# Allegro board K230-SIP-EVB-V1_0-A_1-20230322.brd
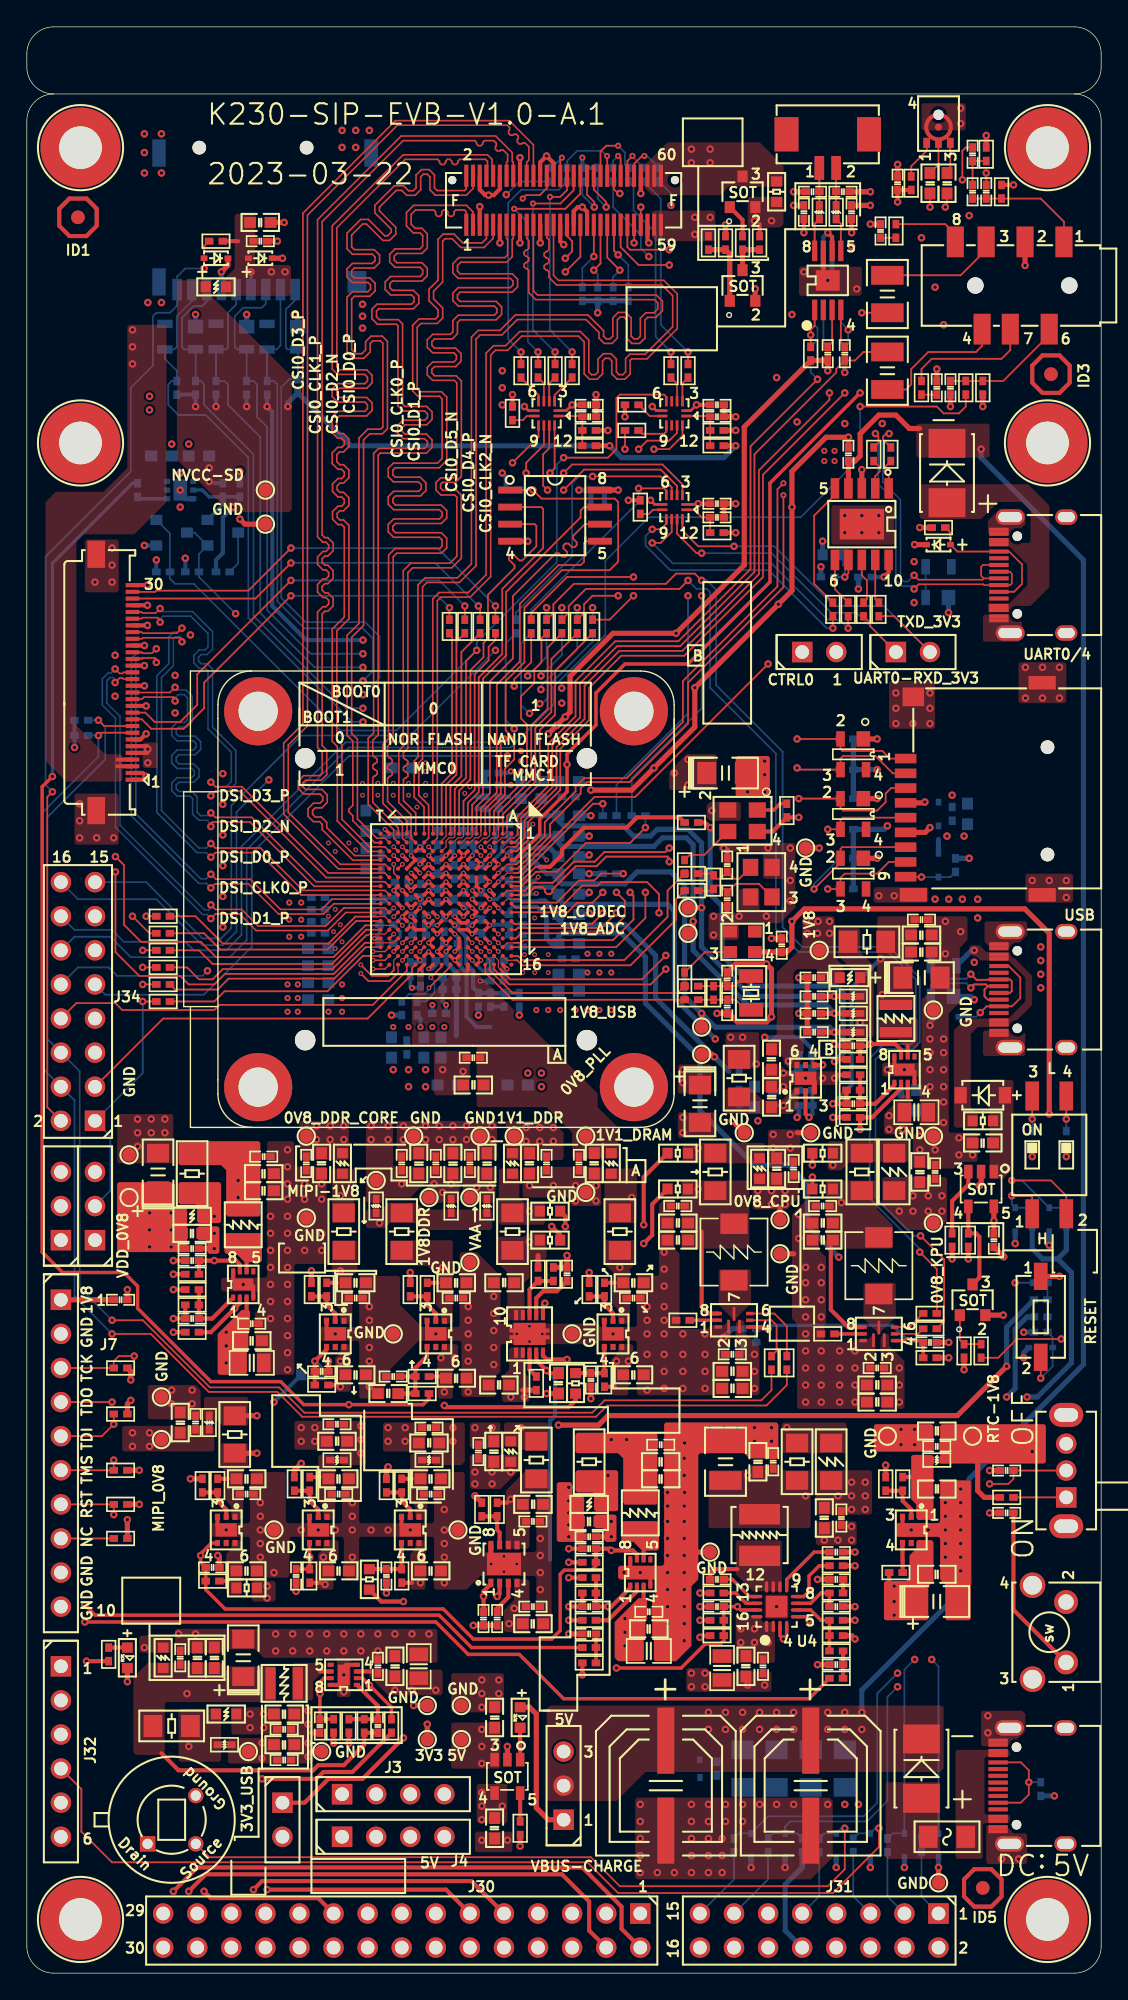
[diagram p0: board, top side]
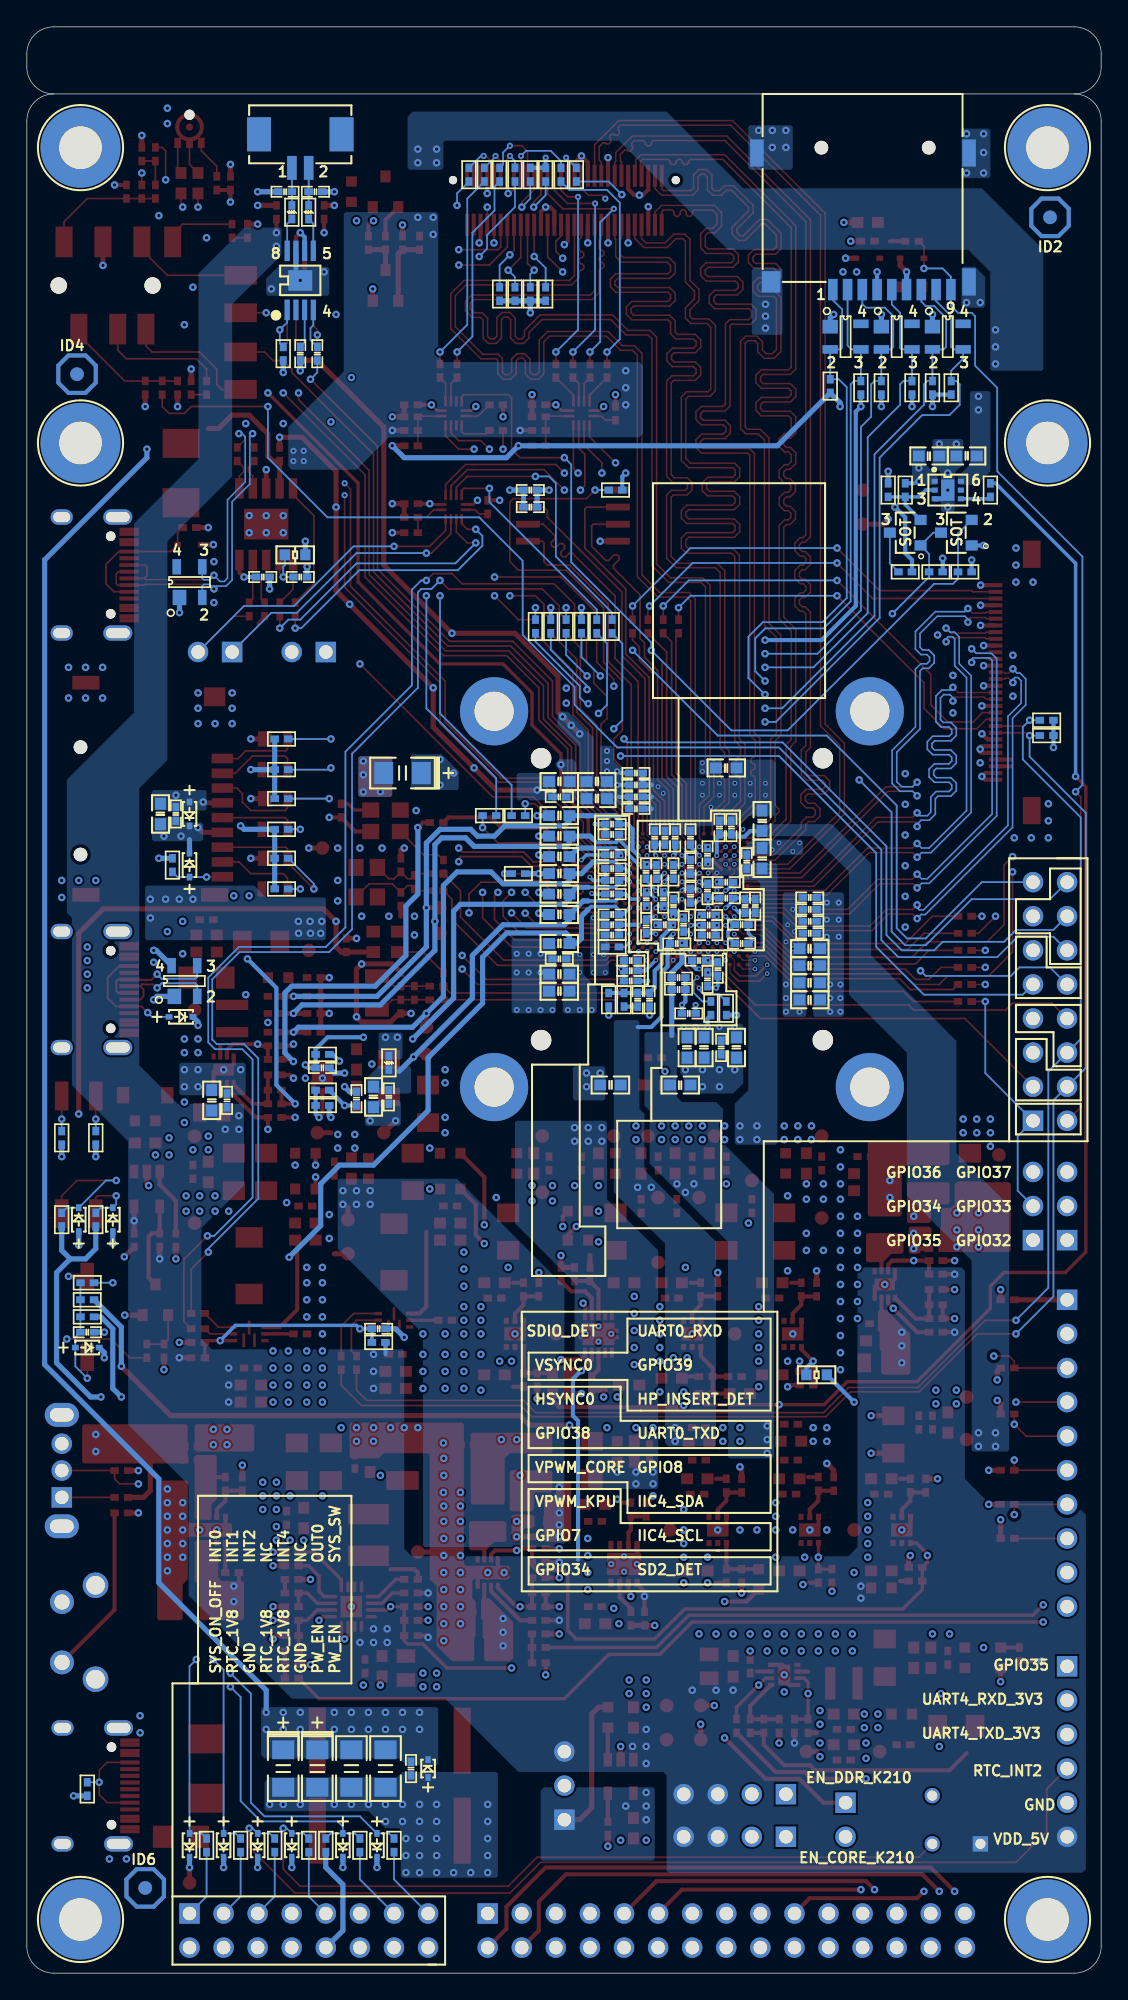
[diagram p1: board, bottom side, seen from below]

Outline 80.07 x 145 mm; copper layers: TOP, GND02, ART03, POWER04, GND05, BOTTOM. Coordinates in mm from the lower left corner of the outline.
Outline path: 2,140 arc(0.59,139.41) 0,138 0,2 arc(0.59,0.59) 2,0 78.07,0 arc(79.48,0.59) 80.07,2 80.07,138 arc(79.48,139.41) 78.07,140 ; 2,140 arc(0.59,140.59) 0,142 0,143 arc(0.59,144.41) 2,145 78.07,145 arc(79.48,144.41) 80.07,143 80.07,142 arc(79.48,140.59) 78.07,140 ; 2,140 78.07,140

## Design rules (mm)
net group ADC0: nets ADC0 HSYNC0
net group ADC1: nets ADC1 VSYNC0
net group ADC2: nets ADC2 N22646851
net group DIFF90: nets USB0_OTG_DN USB0_OTG_DP
net group GPIO20: nets GPIO20 MIPI_DSI_LCD_EN
net group GPIO21: nets GPIO21 MIPI_DSI_D_RST
net group GPIO22: nets GPIO22 MIPI_DSI_T_INT
net group GPIO23: nets GPIO23 MIPI_DSI_T_RST
net group GPIO24_3V3: nets GPIO24_3V3 N22838956
net group GPIO32: nets GPIO32 N22367376
net group GPIO33: nets GPIO33 N22305398
net group GPIO34: nets GPIO34 N22305396
net group GPIO34_1V8: nets GPIO34_1V8 N22897045
net group GPIO35: nets GPIO35 N22305394
net group GPIO35_1V8: nets GPIO35_1V8 N22897025
net group GPIO36: nets GPIO36 N22305392
net group GPIO36_1V8: nets GPIO36_1V8 N22897005
net group GPIO37: nets GPIO37 N22305390
net group GPIO44: nets GPIO44 IIC3_SCL
net group GPIO45: nets GPIO45 IIC3_SDA
net group GPIO48: nets GPIO48 UART4_TXD
net group GPIO49: nets GPIO49 UART4_RXD
net group GPIO59: nets GPIO59 N22647453
net group GPIO60: nets GPIO60 IIC0_SCL
net group GPIO61: nets GPIO61 IIC0_SDA
net group HP_INSERT_DET: nets HP_INSERT_DET N22328764
net group IIC4_SCL: nets IIC4_SCL N23166503
net group IIC4_SDA: nets IIC4_SDA N23166482
net group N22182672: nets N22182672 N22212532
net group N22445143: nets N22445143 N22445145
net group N23147659: nets N23147659 N23147737
net group PG_3V3: nets N23088513 PG_3V3
net group PW_EN: nets N22192931 PW_EN
net group RTC_INT0: nets N22850142 RTC_INT0
net group RTC_INT1: nets N22850140 RTC_INT1
net group RTC_INT2: nets N22850146 RTC_INT2
net group RTC_INT4: nets N22994425 RTC_INT4
net group SYS_SW: nets N22850259 SYS_SW
net group UART0_RXD_3V3: nets N22756731 UART0_RXD_3V3
net group UART0_TXD_3V3: nets N22756757 UART0_TXD_3V3
net group UART4_RXD_3V3: nets N22756876 UART4_RXD_3V3
net group UART4_TXD_3V3: nets N22756879 UART4_TXD_3V3
net group 18MIL: nets JTAG_RST JTAG_TCK M_CLK1 M_CLK2 M_CLK3
net group AVDD1V8_MIPI: nets AVDD1V8_MIPI K230_RSTN RTC_OUT1
net group BUS-QSPI: nets QSPI0_CS0
net group CLK24M_XIN: nets CLK24M_XIN CLK24M_XOUT N22293491 N22778016 N22778033
net group DIFF100: nets DEBUG_DM DEBUG_DP N22756394 N22756396
net group GPIO25: nets GPIO25 N22647230 N228906461
net group GPIO32_1V8: nets GPIO32_1V8 N22647232 N22896944
net group GPIO33_1V8: nets GPIO33_1V8 N22647187 N22896964
net group GPIO37_1V8: nets GPIO37_1V8 N22647219 N22896985
net group GPIO40: nets GPIO40 IIC1_SCL N23166302
net group GPIO41: nets GPIO41 IIC1_SDA N23166270
net group RTC_1V8: nets N22850264 N22850508 RTC_OUT0
net group RTC_CLK_IN: nets N22813541 N22813555 N22813557 RTC_CLK_IN RTC_CLK_OUT

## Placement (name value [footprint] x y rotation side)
C1  330uF/25V  [C1010_8383_6666]  58.42 13.97 180 top
C2  330uF/25V  [C1010_8383_6666]  47.62 13.97 180 top
C3  10uF/16V-1206  [TC1206]  58.42 15.24 270 bottom
C4  10uF/16V-1206  [TC1206]  60.96 15.24 270 bottom
C5  22uF/16V-1206  [C1206]  55.88 15.24 270 bottom
C6  22uF/16V-1206  [C1206]  53.34 15.24 270 bottom
C7  100nF/16V  [C0402]  51.44 15.24 270 bottom
C8  10uF/25V-0603  [C0603]  34.86 10.79 270 top
C9  10uF/25V-0603  [C0603]  34.86 19.05 90 top
C10  10uF/16V-1206  [TC1206]  67.82 27.69 0 top
C11  2.2uF/10V-0603  [C0603]  67.82 29.72 0 top
C12  22uF/6.3V-0603  [C0603]  67.82 36.07 180 top
C13  10uF/10V-0603  [C0603]  67.82 40.39 180 top
C14  100nF/16V  [C0402]  67.82 39.24 180 top
C15  10uF/10V-0603  [C0603]  63.37 42.55 180 top
C16  100nF/16V  [C0402]  63.37 45.09 180 top
C17  10uF/10V-0603  [C0603]  63.37 43.81 180 top
C18  10uF/10V-0603  [C0603]  66.55 59.69 90 top
C19  22uF/6.3V-0603  [C0603]  59.31 54.61 180 top
C20  22uF/6.3V-0603  [C0603]  59.31 55.88 180 top
C21  100nF/16V  [C0402]  67.69 59.69 90 top
C22  100nF/16V  [C0402]  59.31 57.15 180 top
C23  NC  [C0402]  67.31 46.99 0 top
C24  22uF/16V-0805  [C0805]  51.82 22.73 270 top
C25  10uF/10V-0603  [C0603]  53.59 22.86 270 top
C26  100nF/16V  [C0402]  54.86 22.86 90 top
C27  100nF/16V  [C0402]  51.44 29.34 180 top
C28  220uF/6.3V-1210  [C1210]  52.07 38.1 90 top
C29  47uF/6.3V-0603  [C0603]  54.48 38.1 90 top
C30  100nF/16V  [C0402]  55.63 38.1 270 top
C31  10uF/10V-0603  [C0603]  59.44 33.91 270 top
C32  100nF/16V  [C0402]  60.71 33.91 270 top
C35  NC  [C0402]  51.44 27.3 0 top
C36  10nF/16V  [C0402]  60.33 27.3 0 top
C37  10nF/16V  [C0402]  60.33 31.37 0 top
C40  1.2nF/50V  [C0402]  60.33 29.34 180 top
C41  100nF/16V  [C0402]  60.33 22.99 180 top
C42  22uF/6.3V-0603  [C0603]  48.51 54.61 180 top
C43  22uF/6.3V-0603  [C0603]  48.51 55.88 180 top
C44  10uF/10V-0603  [C0603]  52.58 43.56 180 top
C45  10uF/10V-0603  [C0603]  52.58 44.83 180 top
C46  100nF/16V  [C0402]  52.58 46.1 180 top
C47  10uF/10V-0603  [C0603]  55.88 59.94 90 top
C48  100nF/16V  [C0402]  57.15 59.94 90 top
C49  100nF/16V  [C0402]  48.51 57.15 180 top
C50  NC  [C0402]  53.85 48.01 180 bottom
C51  22uF/16V-0805  [C0805]  46.35 24 0 top
C52  10uF/10V-0603  [C0603]  46.35 25.65 0 top
C53  100nF/16V  [C0402]  46.35 26.92 180 top
C54  22pF/50V  [C0402]  41.91 27.3 180 top
C55  22uF/6.3V-0603  [C0603]  47.24 36.83 0 top
C56  22uF/6.3V-0603  [C0603]  47.24 38.1 0 top
C57  100nF/16V  [C0402]  47.24 39.37 180 top
C58  10uF/10V-0603  [C0603]  41.91 33.66 0 top
C59  100nF/16V  [C0402]  41.91 32.51 0 top
C60  NC  [C0402]  41.91 31.62 0 top
C61  100nF/16V  [C0402]  41.91 25.27 0 top
C62  10uF/10V-0603  [C0603]  27.43 22.86 90 top
C63  22uF/16V-0805  [C0805]  29.21 22.86 90 top
C64  100nF/16V  [C0402]  26.16 22.86 270 top
C65  22pF/50V  [C0402]  26.16 18.41 270 top
C66  22uF/6.3V-0603  [C0603]  13.97 23.5 90 top
C67  22uF/6.3V-0603  [C0603]  12.7 23.5 90 top
C68  100nF/16V  [C0402]  11.43 23.5 270 top
C69  10uF/16V-1206  [TC1206]  16.13 23.5 90 top
C70  10uF/10V-0603  [C0603]  19.18 17.02 0 top
C71  100nF/16V  [C0402]  19.18 15.88 0 top
C72  NC  [C0402]  21.84 18.41 90 top
C73  10uF/10V-0603  [C0603]  19.18 19.3 0 top
C74  100nF/16V  [C0402]  19.18 18.16 0 top
C75  10uF/10V-0603  [C0603]  16.76 47.12 0 top
C76  22uF/16V-0805  [C0805]  16.76 45.47 0 top
C77  100nF/16V  [C0402]  16.76 48.39 180 top
C78  22pF/50V  [C0402]  12.32 48.77 180 top
C79  22uF/6.3V-0603  [C0603]  17.65 59.56 0 top
C80  22uF/6.3V-0603  [C0603]  17.65 58.29 0 top
C81  100nF/16V  [C0402]  17.65 60.83 180 top
C82  10uF/10V-0603  [C0603]  12.32 55.12 0 top
C83  100nF/16V  [C0402]  12.32 53.98 0 top
C84  NC  [C0402]  12.32 53.09 0 top
C85  22uF/16V-0805  [C0805]  66.29 64.14 0 top
C86  10uF/10V-0603  [C0603]  66.29 65.02 90 bottom
C87  100nF/16V  [C0402]  65.15 65.02 270 bottom
C88  100nF/16V  [C0402]  58.67 74.17 180 top
C89  22pF/50V  [C0402]  61.59 64.77 180 top
C90  22uF/6.3V-0603  [C0603]  66.67 76.07 0 top
C91  22uF/6.3V-0603  [C0603]  66.67 77.34 0 top
C92  100nF/16V  [C0402]  66.67 78.49 180 top
C93  10uF/16V-1206  [TC1206]  66.67 74.17 0 top
C94  100nF/16V  [C0402]  58.67 70.1 180 top
C95  100nF/16V  [C0402]  58.67 72.77 180 top
C96  NC  [C0402]  61.59 69.09 0 top
C97  100nF/16V  [C0402]  58.67 71.5 180 top
C98  10uF/10V-0603  [C0603]  23.11 39.62 180 top
C99  22uF/6.3V-0603  [C0603]  23.24 29.97 0 top
C100  100nF/16V  [C0402]  23.11 40.89 180 top
C101  22uF/6.3V-0603  [C0603]  23.24 36.83 0 top
C102  100nF/16V  [C0402]  23.24 35.69 0 top
C103  NC  [C0402]  20.07 29.59 270 top
C104  22uF/6.3V-0603  [C0603]  30.1 29.97 0 top
C105  22uF/6.3V-0603  [C0603]  30.1 36.83 0 top
C106  100nF/16V  [C0402]  30.1 35.69 0 top
C107  10uF/10V-0603  [C0603]  29.97 39.5 180 top
C108  100nF/16V  [C0402]  29.97 40.64 180 top
C109  NC  [C0402]  26.8 29.59 270 top
C110  10uF/10V-0603  [C0603]  29.21 60.33 90 top
C111  100nF/16V  [C0402]  27.94 60.33 90 top
C112  22uF/6.3V-0603  [C0603]  32 44.32 0 top
C113  22uF/6.3V-0603  [C0603]  32 51.44 0 top
C114  100nF/16V  [C0402]  32 50.29 0 top
C115  NC  [C0603]  26.92 43.18 180 top
C116  10uF/10V-0603  [C0603]  31.75 60.33 90 top
C117  100nF/16V  [C0402]  30.48 60.33 90 top
C118  100nF/16V  [C0402]  27.3 44.45 180 top
C119  10uF/10V-0603  [C0603]  34.29 60.33 90 top
C120  100nF/16V  [C0402]  33.02 60.33 90 top
C121  22uF/6.3V-0603  [C0603]  24.51 44.58 0 top
C122  22uF/6.3V-0603  [C0603]  24.51 51.44 0 top
C123  10uF/10V-0603  [C0603]  21.97 60.33 270 top
C124  100nF/16V  [C0402]  20.83 60.33 270 top
C125  100nF/16V  [C0402]  24.51 50.29 0 top
C126  NC  [C0402]  21.97 44.83 0 top
C127  22uF/6.3V-0603  [C0603]  16.38 29.97 0 top
C128  22uF/6.3V-0603  [C0603]  16.38 36.83 0 top
C129  100nF/16V  [C0402]  16.38 35.69 0 top
C130  10uF/10V-0603  [C0603]  11.43 41.02 90 top
C131  100nF/16V  [C0402]  12.57 41.02 90 top
C132  NC  [C0402]  13.84 30.23 0 top
C133  4.7uF/16V-0603  [C0603]  35.18 43.81 180 top
C134  4.7uF/16V-0603  [C0603]  35.56 51.44 180 top
C135  10uF/10V-0603  [C0603]  37.47 60.33 270 top
C136  100nF/16V  [C0402]  38.73 60.33 270 top
C137  4.7uF/16V-0603  [C0603]  39.62 43.94 270 top
C138  1nF/50V  [C0402]  40.26 52.07 90 top
C139  4.7uF/16V-0603  [C0603]  37.72 26.04 0 top
C140  100nF/16V  [C0402]  37.72 27.3 0 top
C141  22uF/6.3V-0603  [C0603]  37.72 34.92 180 top
C142  100nF/16V  [C0402]  37.72 33.66 0 top
C143  10uF/10V-0603  [C0603]  34.8 38.86 90 top
C144  100nF/16V  [C0402]  33.66 38.86 90 top
C145  1uF/6.3V  [C0402]  34.04 26.42 270 top
C146  1nF/50V  [C0402]  35.05 26.42 270 top
C147  22uF/6.3V-0603  [C0603]  55.5 68.07 270 top
C148  10uF/10V-0603  [C0603]  54.23 65.28 270 bottom
C149  22uF/6.3V-0603  [C0603]  55.5 65.28 90 top
C150  100nF/16V  [C0402]  53.09 65.28 270 bottom
C151  100nF/16V  [C0402]  55.5 65.15 90 bottom
C152  NC  [C0402]  58.04 67.44 180 bottom
C153  22uF/6.3V-0603  [C0603]  45.21 44.58 0 top
C154  22uF/6.3V-0603  [C0603]  45.21 51.44 0 top
C155  100nF/16V  [C0402]  45.21 50.29 0 top
C156  10uF/10V-0603  [C0603]  42.29 60.33 270 top
C157  100nF/16V  [C0402]  41.15 60.33 270 top
C158  NC  [C0402]  42.04 44.2 270 top
C159  10uF/16V-1206  [TC1206]  9.78 59.69 90 top
C160  10uF/10V-0603  [C0603]  21.72 72.52 180 bottom
C161  10uF/10V-0603  [C0603]  21.72 76.33 180 bottom
C162  100nF/16V  [C0402]  21.72 78.36 180 bottom
C163  100nF/16V  [C0402]  21.72 79.25 180 bottom
C164  100nF/16V  [C0402]  21.72 77.47 180 bottom
C165  100nF/16V  [C0402]  30.61 80.26 270 bottom
C166  100nF/16V  [C0402]  26.54 79.5 90 bottom
C167  100nF/16V  [C0402]  30.61 82.42 90 bottom
C168  10uF/10V-0603  [C0603]  21.72 73.79 180 bottom
C169  10uF/10V-0603  [C0603]  21.72 75.06 180 bottom
C170  100nF/16V  [C0402]  29.34 80.64 90 bottom
C171  100nF/16V  [C0402]  27.94 80.09 180 bottom
C172  100nF/16V  [C0402]  25.78 79.5 90 bottom
C173  100nF/16V  [C0402]  33.91 80.01 270 bottom
C174  100nF/16V  [C0402]  21.72 80.14 180 bottom
C175  10uF/16V-1206  [TC1206]  50.16 64.77 270 top
C176  10uF/10V-0603  [C0603]  40.39 73.15 0 bottom
C177  10uF/10V-0603  [C0603]  40.39 74.42 0 bottom
C178  100nF/16V  [C0402]  40.39 75.56 0 bottom
C179  100nF/16V  [C0402]  32.64 80.01 90 bottom
C180  10uF/16V-1206  [TC1206]  52.07 89.41 0 top
C181  10uF/16V-1206  [TC1206]  52.07 89.41 0 bottom
C182  10uF/10V-0603  [C0603]  37.59 88.77 0 bottom
C183  100nF/16V  [C0402]  34.67 89.41 180 bottom
C184  100nF/16V  [C0402]  34.67 87.63 180 bottom
C185  100nF/16V  [C0402]  31.88 82.04 90 bottom
C186  10uF/10V-0603  [C0603]  37.59 87.5 0 bottom
C187  100nF/16V  [C0402]  33.15 82.04 90 bottom
C188  100nF/16V  [C0402]  34.67 88.52 180 bottom
C189  100nF/16V  [C0402]  34.67 86.74 180 bottom
C190  10uF/10V-0603  [C0603]  27.94 89.79 180 bottom
C191  100nF/16V  [C0402]  26.8 78.11 180 bottom
C192  100nF/16V  [C0402]  30.61 84.58 90 bottom
C193  10uF/10V-0603  [C0603]  40.39 84.71 0 bottom
C194  100nF/16V  [C0402]  36.45 84.84 0 bottom
C195  4.7uF/6.3V-0603  [C0603]  40.39 86.23 0 bottom
C196  100nF/16V  [C0402]  36.45 85.6 0 bottom
C197  10uF/10V-0603  [C0603]  40.39 78.87 0 bottom
C198  100nF/16V  [C0402]  36.45 80.39 0 bottom
C199  10uF/10V-0603  [C0603]  25.27 85.85 90 bottom
C200  100nF/16V  [C0402]  28.45 85.34 90 bottom
C201  100nF/16V  [C0402]  27.56 85.34 90 bottom
C202  10uF/10V-0603  [C0603]  25.27 83.06 90 bottom
C203  100nF/16V  [C0402]  29.34 83.31 90 bottom
C204  100nF/16V  [C0402]  26.42 82.8 90 bottom
C205  10uF/10V-0603  [C0603]  40.39 76.71 0 bottom
C206  100nF/16V  [C0402]  36.45 78.87 0 bottom
C207  10uF/10V-0603  [C0603]  40.39 80.39 0 bottom
C208  100nF/16V  [C0402]  36.45 81.41 0 bottom
C209  4.7uF/6.3V-0603  [C0603]  40.39 81.92 0 bottom
C210  100nF/16V  [C0402]  36.45 82.3 0 bottom
C211  10uF/10V-0603  [C0603]  27.18 68.96 270 bottom
C212  100nF/16V  [C0402]  28.32 68.96 270 bottom
C213  100nF/16V  [C0402]  29.25 78.83 180 bottom
C214  100nF/16V  [C0402]  30.73 71.5 0 bottom
C215  100nF/16V  [C0402]  31.11 78.11 270 bottom
C216  10uF/10V-0603  [C0603]  36.58 66.17 0 bottom
C217  100nF/16V  [C0402]  31.62 76.71 180 bottom
C218  10uF/10V-0603  [C0603]  33.27 66.17 180 top
C219  100nF/16V  [C0402]  29.34 74.04 270 bottom
C220  100nF/16V  [C0402]  33.27 68.2 180 top
C221  10uF/10V-0603  [C0603]  30.86 68.96 270 bottom
C222  100nF/16V  [C0402]  35.05 75.44 0 bottom
C223  100nF/16V  [C0402]  29.25 78.08 180 bottom
C224  100nF/16V  [C0402]  31.88 79.5 90 bottom
C225  100nF/16V  [C0402]  35.05 74.68 0 bottom
C226  10uF/10V-0603  [C0603]  31.37 66.17 180 bottom
C227  100nF/16V  [C0402]  31.5 73.28 180 bottom
C228  100nF/16V  [C0402]  31.5 74.17 180 bottom
C229  100nF/16V  [C0402]  36.45 78.11 0 bottom
C230  100nF/16V  [C0402]  36.45 77.34 0 bottom
C231  10uF/10V-0603  [C0603]  29.59 68.96 270 bottom
C232  100nF/16V  [C0402]  29.25 77.33 180 bottom
C233  100nF/16V  [C0402]  28.57 74.8 270 bottom
C234  100nF/16V  [C0402]  29.97 75.44 0 bottom
C235  100nF/16V  [C0402]  36.45 83.31 0 bottom
C236  4.7uF/6.3V-0603  [C0603]  40.39 83.19 0 bottom
C237  4.7uF/6.3V-0603  [C0603]  40.39 88.77 0 bottom
C238  100nF/16V  [C0402]  75.56 47.75 0 bottom
C239  100nF/16V  [C0402]  40.39 87.63 0 bottom
C240  100nF/16V  [C0402]  33.66 72.52 270 bottom
C241  1nF/50V  [C0402]  32.51 78.11 0 bottom
C242  12pF/50V  [C0402]  52.2 82.55 90 top
C243  12pF/50V  [C0402]  52.2 80.01 270 top
C244  100nF/16V  [C0402]  56.26 76.58 90 top
C245  12pF/50V  [C0402]  52.2 72.01 270 top
C246  12pF/50V  [C0402]  52.2 74.04 90 top
C247  100nF/16V  [C0402]  33.27 84.58 90 bottom
C248  100nF/16V  [C0402]  6.99 50.16 0 top
C249  100nF/16V  [C0402]  33.92 82.04 90 bottom
C250  100nF/16V  [C0402]  32.51 84.58 90 bottom
C251  100nF/16V  [C0402]  26.8 76.71 180 bottom
C253  100nF/16V  [C0402]  31.75 84.58 270 bottom
C254  100nF/16V  [C0402]  41.91 116.84 0 top
C255  100nF/16V  [C0402]  41.91 115.95 180 top
C258  100nF/16V  [C0402]  51.44 116.84 0 top
C259  100nF/16V  [C0402]  51.44 115.95 180 top
C271  100nF/16V  [C0402]  17.4 129.03 0 top
C272  22uF/6.3V-0603  [C0603]  17.4 130.43 0 top
C273  1uF/25V  [C0402]  72.07 54.61 90 top
C274  10uF/10V-0603  [C0603]  71.25 61.85 0 top
C275  1uF/6.3V  [C0402]  70.48 135.51 270 top
C276  10nF/50V  [C0402]  70.48 132.72 270 top
C277  1uF/6.3V  [C0402]  71.5 132.72 270 top
C278  100nF/16V  [C0402]  63.63 129.79 270 top
C279  220uF/6.3V-1210  [C1210]  64.14 119.38 270 top
C280  100nF/16V  [C0402]  67.82 118.11 270 top
C281  220uF/6.3V-1210  [C1210]  64.14 125.09 90 top
C282  100nF/16V  [C0402]  68.83 118.11 270 top
C283  1uF/6.3V  [C0402]  61.47 131.19 270 top
C284  1uF/6.3V  [C0402]  57.91 131.19 270 top
C285  4.7uF/6.3V-0603  [C0603]  67.31 133.35 90 top
C286  100nF/16V  [C0402]  64.9 133.35 270 top
C287  4.7uF/6.3V-0603  [C0603]  68.58 133.35 90 top
C288  100nF/16V  [C0402]  61.23 113.16 90 top
C289  100nF/16V  [C0402]  62.48 104.01 0 bottom
C290  100nF/16V  [C0402]  59.69 104.01 0 bottom
C291  100nF/16V  [C0402]  51.44 109.47 0 top
C292  100nF/16V  [C0402]  51.44 108.46 180 top
C293  100nF/16V  [C0402]  73.03 34.29 180 top
C294  100nF/16V  [C0402]  73.03 37.44 0 top
C295  100nF/16V  [C0402]  60.82 132.72 0 top
C296  100nF/16V  [C0402]  58.56 132.72 180 top
C297  100nF/16V  [C0402]  60.82 132.72 0 bottom
C298  100nF/16V  [C0402]  58.56 132.72 180 bottom
C299  100nF/16V  [C0402]  33.91 77.98 270 bottom
C300  100nF/16V  [C0402]  34.54 72.52 90 bottom
C301  2.2uF/10V-0603  [C0603]  12.83 113.03 180 bottom
C302  2.2uF/10V-0603  [C0603]  10.03 113.03 0 bottom
C303  4.7uF/6.3V  [C0402]  42.55 110.49 180 bottom
C304  100nF/16V  [C0402]  42.55 109.22 180 bottom
C305  100nF/16V  [C0402]  27.94 81.28 0 bottom
C306  100nF/16V  [C0402]  35.05 73.91 0 bottom
C307  39nF/16V  [C0402]  60.96 120.65 90 top
C308  39nF/16V  [C0402]  59.69 120.65 90 top
C309  39nF/16V  [C0402]  58.42 120.65 90 bottom
C310  39nF/16V  [C0402]  59.69 120.65 90 bottom
C311  22uF/6.3V-0603  [C0603]  70.1 86.36 270 bottom
C312  100nF/16V  [C0402]  68.96 86.36 270 bottom
D1  SS24  [D2215-95]  66.67 15.24 90 top
D2  NC  [SOD523-2-28-H]  50.16 15.24 90 bottom
D3  SS24  [D2215-95]  68.58 111.76 90 top
D4  NC  [SOD123FL-2-40]  71.25 65.41 180 top
F1  3A-12V  [F1206]  68.58 10.16 180 top
FB1  600R/300mA  [FB0402]  67.82 38.23 0 top
FB2  30R/4A  [FB1206]  64.64 59.69 90 top
FB3  NC  [FB1206]  59.94 38.1 90 top
FB6  120R/2A  [FB0603]  54.61 59.94 270 top
FB7  NC  [FB0603]  41.91 34.92 180 top
FB8  600R/300mA  [FB0402]  14.73 17.02 0 top
FB9  120R/2A  [FB0603]  14.86 19.3 0 top
FB10  120R/2A  [FB0603]  10.16 23.5 90 top
FB11  70R/3.5A  [FB0603]  12.32 56.39 180 top
FB12  120R/2A  [FB0603]  61.34 74.17 180 top
FB13  600R/300mA  [FB0402]  61.59 70.1 180 top
FB14  600R/300mA  [FB0402]  61.59 72.77 180 top
FB15  600R/300mA  [FB0402]  61.59 71.5 180 top
FB16  NC  [FB0402]  23.11 38.23 0 top
FB17  NC  [FB0402]  29.97 38.23 0 top
FB18  600R/300mA  [FB0402]  26.04 57.15 90 top
FB19  600R/300mA  [FB0402]  31.62 57.15 90 top
FB20  600R/300mA  [FB0402]  34.29 57.15 90 top
FB21  120R/2A  [FB0603]  23.52 60.33 90 top
FB22  600R/300mA  [FB0402]  13.59 41.02 270 top
FB23  120R/2A  [FB0603]  36.2 60.33 90 top
FB24  NC  [FB0603]  36.07 38.86 270 top
FB25  600R/300mA  [FB0402]  53.09 67.82 270 bottom
FB26  120R/2A  [FB0603]  43.56 60.33 90 top
FB29  600R/300mA  [FB0402]  59.07 131.19 90 top
FB30  600R/300mA  [FB0402]  60.32 131.19 90 top
FB31  600R/300mA  [FB0402]  60.31 131.19 90 bottom
FB32  600R/300mA  [FB0402]  59.06 131.19 90 bottom
FB33  NC  [FB0603]  14.1 125.63 180 top
ID1  ID-BOARD  [ID]  3.81 130.81 0 top
ID2  ID-BOARD  [ID]  3.81 130.81 180 bottom
ID3  ID-BOARD  [ID]  76.33 119.13 0 top
ID4  ID-BOARD  [ID]  76.33 119.13 180 bottom
ID5  ID-BOARD  [ID]  71.25 6.35 0 top
ID6  ID-BOARD  [ID]  71.25 6.35 180 bottom
J1  TYPE-C  [TYPE-C-USB16-20-126-H-SMD-B]  76.36 13.95 90 top
J2  3_ 2.54mm  [HEAD3-100]  40.01 11.43 90 top
J3  4pin 2.54mm  [HEAD4-100]  23.5 13.34 0 top
J4  4pin 2.54mm  [HEAD4-100]  23.5 10.16 0 top
J7  10pin 2.54mm  [HEAD10-100]  2.54 42.55 270 top
J11  TYPE-C  [TYPE-C-USB16-20-126-H-SMD-B]  76.42 73.28 90 top
J18  PJ35367  [AUDIO-PJ3536-7-197]  74.3 125.73 270 top
J19  2P-SMD-1.25  [CON2-075053-036]  59.69 137.16 0 top
J20  2P-SMD-1.25  [CON2-075053-036]  59.69 137.16 180 bottom
J21  TH243-G60S-W0R01  [BTB2X30-050-F-SMD]  40.01 132.08 0 top
J22  CON-FPC-30P-0.5PITCH-SMD  [FPC30-005-0520-75]  7.87 96.16 270 top
J27  TYPE-C  [TYPE-C-USB16-20-126-H-SMD-B]  76.42 104.16 90 top
J28  2pin 2.54mm  [HEAD2-100]  64.77 98.42 0 top
J30  2x15PIN_2P54  [HEAD2X15-100]  45.72 4.45 180 top
J31  2X8_2.54mm  [HEAD2X8-100]  67.94 4.45 180 top
J32  6pin 2.54mm  [HEAD6-100]  2.54 22.86 270 top
J33  3_ 2.54mm  [DSEN-PIR-D204B-3-193]  10.79 11.43 180 top
J34  2X8_2.54mm  [HEAD2X8-100]  5.08 63.5 90 top
J35  2pin 2.54mm  [HEAD2-100]  19.05 12.7 270 top
J36  2pin 2.54mm  [HEAD2-100]  57.78 98.42 0 top
J37  3_ 2.54mm  [HEAD3-100]  5.08 54.61 90 top
J38  3_ 2.54mm  [HEAD3-100]  2.54 54.61 90 top
K1  TS-KG07U  [SW2-061036-025]  75.56 48.9 90 top
K2  KH-6X6X8H-ZJ  [DSW4-KH-6X6X7H-ZJ]  76.2 25.4 90 top
K3  SK12D07VG3  [DSW3-087044-047-H]  77.46 37.44 90 top
L1  0.33uH/12A  [PL0505-030]  63.5 52.7 90 top
L2  1uH/5.1A  [PL0404-020]  54.61 32.64 180 top
L3  0.33uH/12A  [PL0505-030]  52.7 53.72 90 top
L4  2.2uH/2.6A  [PL02_502-01]  45.72 34.29 90 top
L5  2.2uH/2.6A  [PL02_502-01]  19.18 21.59 180 top
L6  2.2uH/2.6A  [PL02_502-01]  16.13 55.75 90 top
L7  2.2uH/2.6A  [PL02_502-01]  64.77 71.12 90 top
LED1  RED 0603  [LED0603]  36.77 19.05 270 top
LED2  RED 0603  [LED0603]  7.49 23.5 270 top
M1  M3  [HOLE-M3]  4 114 90 top
M2  M3  [HOLE-M3]  76.07 136 90 top
M3  M3  [HOLE-M3]  76.07 114 90 top
M4  M3  [HOLE-M3]  4 136 90 top
M5  M3  [HOLE-M3]  76.07 4 90 top
M6  M3  [HOLE-M3]  4 4 90 top
NOREF  -  [unnamed]  31.24 80.01 270 top
NOREF#2  -  [#2]  149.22 98.42 0 top
Q1  2N7002  [SOT23-3-43]  14.61 107.31 90 bottom
Q2  2N7002  [SOT23-3-43]  70.48 50.16 0 top
Q3  2N7002  [SOT23-3-43]  10.79 107.31 90 bottom
Q4  2N7002  [SOT23-3-43]  53.34 125.73 0 top
Q5  YJL2301C  [SOT23-3-43]  53.34 132.72 0 top
R1  5.1K/1%  [R0402]  75.56 13.72 270 bottom
R2  1.1K/1%  [R0402]  36.77 10.79 270 top
R3  1K  [R0402]  6.1 23.75 90 top
R4  23.2K/1%  [R0402]  65.28 36.45 90 top
R5  10K  [R0402]  64.77 29.84 0 top
R6  10.2K/1%  [R0402]  64.01 36.45 90 top
R7  0.005R/1%-1206  [R1206]  62.23 59.69 90 top
R8  NC  [R0402]  67.31 45.85 0 top
R9  56.2K/1%  [R0402]  59.69 47.62 180 top
R10  NC  [R0603]  59.31 58.42 0 top
R11  NC  [R0603]  59.31 61.09 0 top
R12  0.005R/1%-1206  [R1206]  57.4 38.1 90 top
R13  22.1K/1%  [R0402]  60.33 26.29 180 top
R14  NC  [R0402]  51.44 25.15 0 top
R15  10K  [R0402]  51.44 28.32 0 top
R16  66.5K/1%  [R0402]  60.33 25.15 0 top
R17  NC  [R0402]  51.44 26.29 180 top
R18  19.1K/1%  [R0402]  60.33 28.32 0 top
R19  34.8K/1%  [R0402]  60.33 30.35 0 top
R20  NC  [R0402]  60.33 24 0 top
R21  10K/1%  [R0402]  60.33 21.97 180 top
R22  0.005R/1%-1206  [R1206]  51.31 59.69 90 top
R23  NC  [R0402]  53.85 46.99 180 bottom
R24  56.2K/1%  [R0402]  48.9 48.64 180 top
R25  NC  [R0603]  48.51 58.42 0 top
R26  NC  [R0603]  48.51 61.09 0 top
R27  0.005R/1%-1206  [R1206]  41.91 38.1 270 top
R28  NC  [R0402]  41.91 30.61 180 top
R29  10K/1%  [R0402]  41.91 28.32 180 top
R30  10K  [R0402]  41.91 26.29 0 top
R31  30K/1%  [R0402]  41.91 29.46 180 top
R32  NC  [R0402]  41.91 23.11 0 top
R33  10K/1%  [R0402]  41.91 24.26 180 top
R34  0.05R/1%_1206  [R1206]  10.79 18.41 0 top
R35  NC  [R0402]  22.86 18.41 270 top
R36  90.9K/1%  [R0402]  25.15 18.41 270 top
R37  10K  [R0402]  27.18 18.41 90 top
R38  20K/1%  [R0402]  24 18.41 90 top
R40  0.005R/1%-1206  [R1206]  12.32 59.56 270 top
R41  10K/1%  [R0402]  12.32 49.78 180 top
R42  10K  [R0402]  12.32 47.75 0 top
R43  NC  [R0402]  12.32 52.07 180 top
R44  30K/1%  [R0402]  12.32 50.93 180 top
R45  0.005R/1%-1206  [R1206]  62.61 76.83 180 top
R46  20K/1%  [R0402]  61.59 65.79 180 top
R47  10K  [R0402]  61.59 63.75 0 top
R48  10K/1%  [R0402]  61.59 66.93 0 top
R49  NC  [R0402]  61.59 68.07 180 top
R50  NC  [R0402]  21.08 29.59 270 top
R51  31.6K/1%  [R0402]  21.08 36.45 270 top
R52  13.7K/1%  [R0402]  19.94 36.45 270 top
R53  NC  [R0402]  27.94 29.59 270 top
R54  31.6K/1%  [R0402]  27.94 36.32 270 top
R55  13.7K/1%  [R0402]  26.8 36.32 90 top
R56  0.5R/1%_1206  [R1206]  27.94 55.24 90 top
R57  NC  [R0402]  29.46 44.45 0 top
R58  31.6K/1%  [R0402]  29.84 50.93 270 top
R59  13.7K/1%  [R0402]  28.57 50.93 90 top
R60  1K  [R0402]  29.46 43.18 0 top
R61  0.05R/1%_1206  [R1206]  23.62 55.24 90 top
R62  20K/1%  [R0402]  22.35 50.93 270 top
R63  10K  [R0402]  21.97 43.81 0 top
R64  0R-0603  [R0603]  21.21 44.58 0 bottom
R65  44.2K/1%  [R0402]  21.21 50.93 90 top
R66  0.5R/1%_1206  [R1206]  15.49 40.13 90 top
R67  NC  [R0402]  13.84 29.21 0 top
R68  20K/1%  [R0402]  14.22 36.32 270 top
R69  44.2K/1%  [R0402]  13.08 36.32 90 top
R70  0.05R/1%_1206  [R1206]  36.2 55.24 90 top
R71  2.49K/1%  [R0402]  38.1 52.07 270 top
R72  6.65K/1%  [R0402]  39.24 52.07 90 top
R73  10K  [R0402]  37.97 43.94 270 top
R74  0R-0603  [R0603]  38.99 54.61 180 top
R75  0R-0603  [R0603]  38.99 56.77 180 top
R76  0.05R/1%_1206  [R1206]  37.97 38.23 90 top
R77  12K/1%  [R0402]  35.05 34.54 270 top
R78  17.4K/1%  [R0402]  33.91 34.54 90 top
R79  0.05R/1%_1206  [R1206]  53.09 66.67 90 top
R80  NC  [R0402]  58.04 68.45 180 bottom
R81  20K/1%  [R0402]  58.04 65.79 0 bottom
R82  44.2K/1%  [R0402]  58.04 64.64 180 bottom
R83  0.05R/1%_1206  [R1206]  44.2 55.24 90 top
R84  10K  [R0402]  43.05 44.2 270 top
R85  100K/1%  [R0402]  43.05 50.93 270 top
R86  0R-0603  [R0603]  40.89 43.94 90 top
R87  100K/1%  [R0402]  41.91 50.93 90 top
R89  NC  [R0402]  75.56 48.9 0 bottom
R90  10K  [R0402]  75.56 50.16 0 bottom
R91  4.99K/1%/NC  [R0402]  36.45 76.45 0 bottom
R92  NC  [R0402]  75.56 51.44 0 bottom
R93  240R/1%  [R0402]  27.94 71.88 270 bottom
R94  240R/1%  [R0402]  29.08 71.88 270 bottom
R95  100R/1%  [R0402]  35.56 72.52 90 bottom
R96  10K  [R0402]  56.64 86.61 270 top
R97  NC  [R0402]  49.02 82.42 270 top
R98  100R/1%  [R0402]  36.7 72.52 270 bottom
R99  1K  [R0402]  74.93 56.13 270 bottom
R100  0R  [R0402]  49.53 81.92 180 top
R101  1K  [R0402]  77.47 56.13 270 bottom
R102  1M  [R0402]  51.18 81.28 270 top
R103  0R  [R0402]  74.93 62.23 270 bottom
R104  0R  [R0402]  77.47 62.23 270 bottom
R105  0R  [R0402]  49.53 80.64 180 top
R106  0R  [R0402]  49.53 72.52 0 top
R107  0R  [R0402]  49.53 73.53 180 top
R108  NC  [R0402]  49.02 74.04 270 top
R109  1M  [R0402]  51.18 73.03 90 top
R110  0R  [R0402]  39.88 100.33 90 top
R111  0R  [R0402]  38.73 100.33 90 top
R112  0R  [R0402]  41.02 100.33 90 top
R113  0R  [R0402]  42.16 100.33 90 top
R114  0R  [R0402]  39.88 100.33 90 bottom
R115  0R  [R0402]  10.16 74.93 180 top
R116  0R  [R0402]  10.16 78.74 180 top
R117  0R  [R0402]  37.59 100.33 90 top
R118  0R  [R0402]  10.16 72.39 180 top
R119  0R  [R0402]  10.16 73.66 180 top
R120  0R  [R0402]  10.16 76.2 180 top
R121  0R  [R0402]  10.16 77.47 180 top
R122  NC  [R0402]  6.99 32.38 180 top
R123  4.7K  [R0402]  6.99 34.92 180 top
R124  4.7K  [R0402]  6.99 37.47 180 top
R125  4.7K  [R0402]  6.99 41.66 180 top
R126  4.7K  [R0402]  6.99 45.09 180 top
R127  0R  [R0402]  42.16 100.33 270 bottom
R128  0R  [R0402]  40.64 119.38 270 top
R129  0R  [R0402]  39.37 119.38 270 top
R130  0R  [R0402]  38.1 119.38 270 top
R131  0R  [R0402]  36.83 119.38 270 top
R132  4.7K  [R0402]  36.2 116.2 270 top
R133  0R  [R0402]  49.28 119.38 270 top
R134  0R  [R0402]  48.01 119.38 270 top
R135  NC  [R0402]  45.09 114.94 180 top
R136  4.7K  [R0402]  45.09 116.84 0 top
R137  30K/1%  [R0402]  49.53 85.72 180 top
R138  200R/1%  [R0402]  43.43 81.92 0 bottom
R139  NC  [R0402]  41.02 100.33 270 bottom
R140  200R/1%  [R0402]  38.73 100.33 270 bottom
R155  10K  [R0402]  14.1 129.03 180 top
R156  10K  [R0402]  14.1 118.11 90 bottom
R157  10K  [R0402]  16.38 118.11 90 bottom
R158  10K  [R0402]  17.91 118.11 90 bottom
R159  10K  [R0402]  20.19 118.24 90 bottom
R160  10K  [R0402]  11.18 118.11 90 bottom
R161  10K  [R0402]  12.57 118.11 90 bottom
R162  10K  [R0402]  70.17 54.61 90 top
R163  20K/1%  [R0402]  68.96 54.61 270 top
R164  0R  [R0402]  71.5 135.51 90 top
R165  2K/1%  [R0402]  72.64 132.72 270 top
R166  10R/1%  [R0402]  64.77 129.79 90 top
R167  10R/1%  [R0402]  66.67 118.11 90 top
R168  10K  [R0402]  71.25 118.11 90 top
R169  0R  [R0402]  69.98 118.11 90 top
R170  10K  [R0402]  58.42 120.65 90 top
R171  10K  [R0402]  60.96 120.65 90 bottom
R172  2K/1%  [R0402]  65.91 133.35 270 top
R173  0R  [R0402]  39.12 133.99 270 bottom
R174  0R  [R0402]  44.83 133.99 270 bottom
R175  0R  [R0402]  40.26 133.99 270 bottom
R176  0R  [R0402]  43.69 133.99 270 bottom
R177  0R  [R0402]  45.97 133.99 270 bottom
R178  0R  [R0402]  47.12 133.99 270 bottom
R179  4.7K/1%  [R0402]  41.4 133.99 270 bottom
R180  4.7K/1%  [R0402]  42.55 133.99 270 bottom
R181  4.7K/1%  [R0402]  43.69 125.09 90 bottom
R182  4.7K/1%  [R0402]  44.83 125.09 90 bottom
R183  4.7K/1%  [R0402]  42.55 125.09 90 bottom
R184  4.7K/1%  [R0402]  41.4 125.09 90 bottom
R185  4.7K/1%  [R0402]  4.06 92.2 0 bottom
R186  4.7K/1%  [R0402]  4.06 93.34 0 bottom
R187  10R/1%  [R0402]  64.39 113.16 270 top
R188  10R/1%  [R0402]  63.12 113.16 270 top
R189  0R  [R0402]  62.36 101.6 270 top
R190  0R  [R0402]  63.5 101.6 270 top
R191  0R  [R0402]  60.07 101.6 270 top
R192  0R  [R0402]  61.21 101.6 270 top
R193  5.1K/1%  [R0402]  67.94 107.7 180 top
R194  0R  [R0603]  60.07 105.66 180 bottom
R195  4.7K  [R0402]  45.72 109.22 270 top
R196  0R  [R0402]  66.67 9.53 270 bottom
R197  0R  [R0402]  61.59 9.53 270 bottom
R198  0R  [R0402]  64.14 9.53 270 bottom
R199  0R  [R0402]  59.05 9.53 270 bottom
R200  0R  [R0402]  55.24 9.53 270 bottom
R201  0R  [R0402]  52.7 9.53 270 bottom
R202  10K  [R0402]  57.78 9.53 270 bottom
R203  10K  [R0402]  73.03 35.44 180 top
R204  0R  [R0402]  51.44 107.31 0 top
R207  0R-0603  [R0603]  16.38 28.7 180 top
R208  10.2K/1%  [R0402]  15.88 110.49 90 bottom
R209  51.1K/1%  [R0402]  14.61 110.49 270 bottom
R210  42.2K/1%  [R0402]  14.61 104.39 0 bottom
R211  10K  [R0402]  8.26 110.49 270 bottom
R212  4.7K/1%  [R0402]  36.2 110.49 0 bottom
R213  0R  [R0402]  34.92 100.33 90 top
R214  0R  [R0402]  33.78 100.33 90 top
R215  0R  [R0402]  31.5 100.33 90 top
R216  0R  [R0402]  32.64 100.33 90 top
R218  0R  [R0402]  36.45 100.33 90 bottom
R219  0R  [R0402]  37.59 100.33 90 bottom
R220  10K  [R0402]  69.85 46.35 90 top
R221  1.5K  [R0402]  71.12 46.35 90 top
R222  10K  [R0402]  10.16 104.39 0 bottom
R223  10K  [R0402]  12.32 104.39 0 bottom
R224  NC  [R0402]  41.91 114.94 0 top
R225  0R  [R0402]  41.91 113.79 0 top
R226  NC  [R0402]  51.44 114.94 0 top
R227  0R  [R0402]  51.44 113.79 0 top
R229  0R  [R0402]  45.59 86.23 180 bottom
R230  0R  [R0402]  43.43 86.23 0 bottom
R231  0R-0603  [R0603]  25.53 29.34 90 top
R263  0R  [R0402]  53.34 128.91 90 top
R264  NC  [R0603]  55.88 132.72 90 top
R265  0R  [R0402]  50.8 128.91 270 top
R266  5.1K/1%  [R0402]  54.61 128.91 90 top
R267  100K  [R0402]  52.07 128.91 90 top
R268  0R  [R0402]  67.31 48.01 180 top
R269  0R  [R0402]  67.31 49.15 180 top
R270  0R  [R0402]  55.5 45.47 90 top
R271  0R  [R0402]  56.64 45.47 90 top
R272  0R-0603  [R0603]  71.25 63.5 180 top
R273  10K  [R0402]  61.09 87.5 180 bottom
R274  10K  [R0402]  61.09 85.22 180 bottom
R275  10K  [R0402]  61.09 89.66 180 bottom
R276  10K  [R0402]  61.09 80.77 180 bottom
R277  10K  [R0402]  61.09 91.95 180 bottom
R278  10K  [R0402]  61.09 83.06 180 bottom
R279  10K  [R0402]  69.22 82.55 270 bottom
SW1  KF1027B-02P-G00-ON-01B  [SW4-100-060050-035]  76.2 60.96 0 top
TP1  DI  [TP40]  67.56 55.88 0 top
TP2  DI  [TP40]  70.48 40.01 0 top
TP3  DI  [TP40]  32.38 17.4 0 top
TP4  DI  [TP40]  56.13 56.13 0 top
TP5  DI  [TP40]  16.51 16.51 0 top
TP6  DI  [TP40]  29.84 17.4 0 top
TP8  DI  [TP40]  7.62 57.78 0 top
TP9  DI  [TP40]  59.05 76.2 0 top
TP10  DI  [TP40]  50.29 70.48 0 top
TP11  DI  [TP40]  49.28 79.38 0 top
TP12  DI  [TP40]  49.28 77.47 0 top
TP13  DI  [TP40]  29.97 57.78 0 top
TP14  DI  [TP40]  33.02 57.78 0 top
TP15  DI  [TP40]  26.04 59.05 0 top
TP16  DI  [TP40]  17.78 110.49 0 top
TP17  DI  [TP40]  20.83 62.36 0 top
TP18  DI  [TP40]  10.03 39.75 0 top
TP19  DI  [TP40]  36.32 62.36 0 top
TP20  DI  [TP40]  50.29 68.45 0 top
TP21  DI  [TP40]  41.66 62.36 0 top
TP22  DI  [TP40]  10.03 42.93 0 top
TP23  DI  [TP40]  17.78 107.95 0 top
TP24  DI  [TP40]  64.14 40.01 0 top
TP25  DI  [TP40]  58.42 62.61 0 top
TP26  DI  [TP40]  67.94 6.73 0 top
TP27  DI  [TP40]  32.13 33.02 0 top
TP28  DI  [TP40]  67.56 71.75 0 top
TP29  DI  [TP40]  18.41 33.02 0 top
TP30  DI  [TP40]  41.66 58.17 0 top
TP31  DI  [TP40]  33.02 52.96 0 top
TP32  DI  [TP40]  20.83 56.26 0 top
TP33  DI  [TP40]  28.83 62.36 0 top
TP34  DI  [TP40]  50.93 31.37 0 top
TP35  DI  [TP40]  33.78 62.36 0 top
TP36  DI  [TP40]  40.64 47.62 0 top
TP37  DI  [TP40]  27.3 47.62 0 top
TP38  DI  [TP40]  53.47 62.61 0 top
TP39  DI  [TP40]  56.13 53.59 0 top
TP40  DI  [TP40]  7.62 60.96 0 top
TP41  DI  [TP40]  29.84 19.94 0 top
TP42  DI  [TP40]  21.97 16.51 0 top
TP43  DI  [TP40]  58.04 83.82 0 top
TP44  DI  [TP40]  67.56 62.36 0 top
TP45  DI  [TP40]  32.38 19.94 0 top
TVS1  ESD5B5.0ST1G  [SOD523-2-28]  75.56 46.61 180 bottom
TVS2  ESD5B5.0ST1G  [SOD523-2-28]  76.2 56.13 90 bottom
TVS3  ESD5B5.0ST1G  [SOD523-2-28]  73.66 56.13 90 bottom
TVS4  ESD5B5.0ST1G  [SOD523-2-28]  14.1 127.76 0 top
TVS5  ESD5B5.0ST1G  [SOD523-2-28]  17.4 127.76 0 top
TVS6  ESD5B5.0ST1G  [SOD523-2-28]  68.58 71.25 180 bottom
TVS7  ESD5B5.0ST1G  [SOD523-2-28]  67.94 106.43 180 top
TVS8  ESD5B5.0ST1G  [SOD523-2-28]  67.94 9.53 270 bottom
TVS9  ESD5B5.0ST1G  [SOD523-2-28]  65.41 9.53 270 bottom
TVS10  ESD5B5.0ST1G  [SOD523-2-28]  62.87 9.53 270 bottom
TVS11  ESD5B5.0ST1G  [SOD523-2-28]  60.33 9.53 270 bottom
TVS12  ESD5B5.0ST1G  [SOD523-2-28]  56.52 9.53 270 bottom
TVS13  ESD5B5.0ST1G  [SOD523-2-28]  53.98 9.53 270 bottom
TVS14  ESD5B5.0ST1G  [SOD523-2-28]  67.94 86.36 270 bottom
TVS15  ESD5B5.0ST1G  [SOD523-2-28]  67.94 82.55 90 bottom
U1  TMI4054-TMI4054H  [SOT23-5-57]  35.81 14.66 180 top
U2  TLV75801PDRVR  [DFN6-065-0202-008-N]  65.91 33.02 270 top
U3  TPS628681A  [QFN9-050-025015-010]  63.5 47.62 90 top
U4  TPS54519RTET  [QFN16-050-0303-008-N]  55.88 27.3 90 top
U5  TPS628681A  [QFN9-050-025015-010]  52.7 48.64 90 top
U6  SY8003EDFC  [QFN8-050-0202-008-N]  45.72 29.84 0 top
U7  SY8003EDFC  [QFN8-050-0202-008-N]  23.62 22.23 90 top
U8  SY8003EDFC  [QFN8-050-0202-008-N]  16.13 51.31 0 top
U9  SY8003EDFC  [QFN8-050-0202-008-N]  65.41 67.31 0 top
U10  TLV75801PDRVR  [DFN6-065-0202-008-N]  21.72 33.02 270 top
U11  TLV75801PDRVR  [DFN6-065-0202-008-N]  28.57 33.02 270 top
U12  TLV75801PDRVR  [DFN6-065-0202-008-N]  30.48 47.62 270 top
U13  TLV75801PDRVR  [DFN6-065-0202-008-N]  22.99 47.62 270 top
U14  TLV75801PDRVR  [DFN6-065-0202-008-N]  14.86 33.02 270 top
U15  TPS74801DRC  [DFN10-050-0303-010-N]  37.47 47.62 90 top
U16  TPS7A7401DSDR  [WSON8-065-0303-008-N]  35.56 30.48 90 top
U17  TLV75801PDRVR  [DFN6-065-0202-008-N]  58.04 66.67 90 top
U18  TLV75801PDRVR  [DFN6-065-0202-008-N]  43.69 47.62 270 top
U19  K230-SIP  [BGA256-065-1111-020]  31.24 80.01 270 top
U20  SGM4574YUQN12G  [QFN12-040-018018-006]  38.73 116.2 180 top
U21  SGM4574YUQN12G  [QFN12-040-018018-006]  48.26 116.2 180 top
U23  CONN_SD_CARD 9  [CARD-MICRO-SD-9-80]  17.78 133.35 0 bottom
U24  PRTR5V0U2X  [SOT143-4-48]  15.24 121.92 270 bottom
U25  PRTR5V0U2X  [SOT143-4-48]  19.05 121.92 270 bottom
U26  PRTR5V0U2X  [SOT143-4-48]  11.43 121.92 270 bottom
U27  DIO7002AST5  [SOT23-5-36]  71.12 58.42 180 top
U29  PRTR5V0U2X  [SOT143-4-48]  68.33 73.91 180 bottom
U30  AW8055MPR  [SOP8-26-120-43-N]  59.69 126.11 90 top
U31  AW8055MPR  [SOP8-26-120-43-N]  59.69 126.11 90 bottom
U32  ICS-40720  [MIC4-030040-012]  67.94 137.79 90 top
U33  CH342K  [SOP10-40-153]  62.23 107.95 180 top
U34  PRTR5V0U2X  [SOT143-4-48]  67.94 103.63 180 bottom
U35  SGM4574YUQN12G  [QFN12-040-018018-006]  48.26 109.22 180 top
U36  TLV75801PDRVR  [DFN6-065-0202-008-N]  11.43 110.49 180 bottom
U37  GD25LQ128D  [SOP8-50-210-85]  39.37 108.58 270 top
U38  PRTR5V0U2X  [SOT143-4-48]  61.59 86.36 180 top
U39  PRTR5V0U2X  [SOT143-4-48]  61.59 90.81 180 top
U40  PRTR5V0U2X  [SOT143-4-48]  61.59 81.92 180 top
U41  CONN_SD_CARD 9  [CARD-MICRO-SD-9-80]  73.42 88.27 90 top
Y1  24MHz/1.8V-3225  [X4-3225-009]  53.34 85.85 180 top
Y2  24MHz  [X4-3225-009]  54.74 81.28 270 top
Y3  32.768KHZ  [X2-3215-008]  53.98 73.03 90 top
Y4  32.768KHz/1.8V-2520  [X4-2520-010]  53.34 76.83 180 top

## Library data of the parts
C1-C4 C10 C69 C93 C159 C175 C180 C181 = CAP POL
C5-C9 C11-C32 C35-C37 C40-C68 C70-C92 C94-C158 C160-C174 C176-C179 C182-C251 C253-C255 C258 C259 C271-C312 = CAP NP
D1 D3 D4 = DIODE SCHOTTKY
D2 = MM5Z5V6ST1G
F1 = 3A-12V
FB1-FB3 FB6-FB26 FB29-FB33 = FB
ID1-ID6 = ID-BOARD
J1 J11 J27 = type-c-smd
J2 J33 J37 J38 = CON3
J3 J4 = CON4
J7 = CON10
J18 = PJ35367
J19 J20 = 2P-SMD-1.25
J21 = TH243-G60S-W0R01
J22 = 30PIN_CONNECT_2D54MM_FPC
J28 J35 J36 = CON2
J30 = 2x15PIN_2P54
J31 J34 = CON2X8
J32 = CON6
K1 = TS-KG07U
K2 = KH-6X6X8H-ZJ
K3 = SK12D07VG3
L1-L7 = INDUCTOR
LED1 LED2 = LED
M1-M6 = M3
Q1-Q4 = 2N7002
Q5 = YJL2301C
R1-R3 R7 R9-R13 R16 R18 R19 R21 R22 R24-R27 R29 R31 R33 R36 R38 R40 R41 R44-R46 R48 R51 R52 R54 R55 R58-R60 R62 R64 R65 R68 R69 R72 R74 R75 R77 R78 R81 R82 R85-R87 R91 R95 R98 R99 R101 R123-R126 R132 R136-R138 R140 R163 R165-R167 R172 R179-R188 R193-R195 R207 R212 R221 R231 R264 R266 R267 R272 = Resistor
R4 R6 R71 R93 R94 R208-R210 R273-R279 = RESISTOR
R5 R15 R30 R37 R42 R47 R63 R73 R84 R90 R96 R155-R162 R168 R170 R171 R202 R203 R211 R220 R222 R223 = RESISTOR: signal model: RESISTOR_R0402_10K_10K
R8 R14 R17 R20 R23 R28 R32 R35 R43 R49 R50 R53 R57 R67 R80 R89 R92 R97 R108 R122 R135 R139 R224 R226 = RESISTOR: signal model: RESISTOR_R0402_NC_NC
R34 R61 R70 R76 R79 R83 = Resistor_50mR
R56 R66 = Resistor_0.5R
R100 R103-R107 R110-R121 R127-R131 R133 R134 R164 R169 R173-R178 R189-R192 R196-R201 R204 R213-R216 R218 R219 R225 R227 R229 R230 R263 R265 R268-R271 = RESISTOR: signal model: RESISTOR_R0402_0R_0R
R102 R109 = Resistor: signal model: RESISTOR_R0402_NC_NC
SW1 = SW_SMD_2P54
TP1-TP6 TP8-TP45 = T POINT S
TVS1-TVS15 = DIODE_TVS_BIDIR
U1 = TMI4054-TMI4054H
U2 U10-U14 U17 U18 U36 = IC_LDO_TLV758P
U3 U5 = TPS628681A
U4 = TPS54519RTET
U6-U9 = SY8003EDFC
U15 = TPS74801DRC
U16 = TPS7A7401DSDR
U19 = K230-SIP
U20 U21 U35 = SGM4574YUQN12G
U23 U41 = CONN_MICRO_SDCARD_9P
U24-U26 U29 U34 U38-U40 = PRTR5V0U2X
U27 = DIO7002AST5
U30 U31 = AW8055MPR
U32 = ICS-40720
U33 = CH342K
U37 = W25Q128
Y1 Y4 = OSC_4
Y2 = Crystal_4
Y3 = Crystal_2

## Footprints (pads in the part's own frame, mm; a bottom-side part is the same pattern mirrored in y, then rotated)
AUDIO-PJ3536-7-197
  round 1.219 hole 1.219 unplated: (0,3.4) (0,-3.6)
  rect 2.286x1.27 smd: 1(-3.25,3) 2(-3.25,0.1) 3(-3.25,-2.8) 4(3.25,-3.1) 6(3.25,1.9) 7(3.25,-1) 8(-3.25,-5.1)
BGA256-065-1111-020
  round 0.305 smd: A1(-4.875,4.875) A2(-4.225,4.875) A3(-3.575,4.875) A4(-2.925,4.875) A5(-2.275,4.875) A6(-1.625,4.875) A7(-0.975,4.875) A8(-0.325,4.875) A9(0.325,4.875) A10(0.975,4.875) A11(1.625,4.875) A12(2.275,4.875) A13(2.925,4.875) A14(3.575,4.875) A15(4.225,4.875) A16(4.875,4.875) B1(-4.875,4.225) B2(-4.225,4.225) B3(-3.575,4.225) B4(-2.925,4.225) B5(-2.275,4.225) B6(-1.625,4.225) B7(-0.975,4.225) B8(-0.325,4.225) B9(0.325,4.225) B10(0.975,4.225) B11(1.625,4.225) B12(2.275,4.225) B13(2.925,4.225) B14(3.575,4.225) B15(4.225,4.225) B16(4.875,4.225) C1(-4.875,3.575) C2(-4.225,3.575) C3(-3.575,3.575) C4(-2.925,3.575) C5(-2.275,3.575) C6(-1.625,3.575) C7(-0.975,3.575) C8(-0.325,3.575) C9(0.325,3.575) C10(0.975,3.575) C11(1.625,3.575) C12(2.275,3.575) C13(2.925,3.575) C14(3.575,3.575) C15(4.225,3.575) C16(4.875,3.575) D1(-4.875,2.925) D2(-4.225,2.925) D3(-3.575,2.925) D4(-2.925,2.925) D5(-2.275,2.925) D6(-1.625,2.925) D7(-0.975,2.925) D8(-0.325,2.925) D9(0.325,2.925) D10(0.975,2.925) D11(1.625,2.925) D12(2.275,2.925) D13(2.925,2.925) D14(3.575,2.925) D15(4.225,2.925) D16(4.875,2.925) E1(-4.875,2.275) E2(-4.225,2.275) E3(-3.575,2.275) E4(-2.925,2.275) E5(-2.275,2.275) E6(-1.625,2.275) E7(-0.975,2.275) E8(-0.325,2.275) E9(0.325,2.275) E10(0.975,2.275) E11(1.625,2.275) E12(2.275,2.275) E13(2.925,2.275) E14(3.575,2.275) E15(4.225,2.275) E16(4.875,2.275) F1(-4.875,1.625) F2(-4.225,1.625) F3(-3.575,1.625) F4(-2.925,1.625) F5(-2.275,1.625) F6(-1.625,1.625) F7(-0.975,1.625) F8(-0.325,1.625) F9(0.325,1.625) F10(0.975,1.625) F11(1.625,1.625) F12(2.275,1.625) F13(2.925,1.625) F14(3.575,1.625) F15(4.225,1.625) F16(4.875,1.625) G1(-4.875,0.975) G2(-4.225,0.975) G3(-3.575,0.975) G4(-2.925,0.975) G5(-2.275,0.975) G6(-1.625,0.975) G7(-0.975,0.975) G8(-0.325,0.975) G9(0.325,0.975) G10(0.975,0.975) G11(1.625,0.975) G12(2.275,0.975) G13(2.925,0.975) G14(3.575,0.975) G15(4.225,0.975) G16(4.875,0.975) H1(-4.875,0.325) H2(-4.225,0.325) H3(-3.575,0.325) H4(-2.925,0.325) H5(-2.275,0.325) H6(-1.625,0.325) H7(-0.975,0.325) H8(-0.325,0.325) H9(0.325,0.325) H10(0.975,0.325) H11(1.625,0.325) H12(2.275,0.325) H13(2.925,0.325) H14(3.575,0.325) H15(4.225,0.325) H16(4.875,0.325) J1(-4.875,-0.325) J2(-4.225,-0.325) J3(-3.575,-0.325) J4(-2.925,-0.325) J5(-2.275,-0.325) J6(-1.625,-0.325) J7(-0.975,-0.325) J8(-0.325,-0.325) J9(0.325,-0.325) J10(0.975,-0.325) J11(1.625,-0.325) J12(2.275,-0.325) J13(2.925,-0.325) J14(3.575,-0.325) J15(4.225,-0.325) J16(4.875,-0.325) K1(-4.875,-0.975) K2(-4.225,-0.975) K3(-3.575,-0.975) K4(-2.925,-0.975) K5(-2.275,-0.975) K6(-1.625,-0.975) K7(-0.975,-0.975) K8(-0.325,-0.975) K9(0.325,-0.975) K10(0.975,-0.975) K11(1.625,-0.975) K12(2.275,-0.975) K13(2.925,-0.975) K14(3.575,-0.975) K15(4.225,-0.975) K16(4.875,-0.975) L1(-4.875,-1.625) L2(-4.225,-1.625) L3(-3.575,-1.625) L4(-2.925,-1.625) L5(-2.275,-1.625) L6(-1.625,-1.625) L7(-0.975,-1.625) L8(-0.325,-1.625) L9(0.325,-1.625) L10(0.975,-1.625) L11(1.625,-1.625) L12(2.275,-1.625) L13(2.925,-1.625) L14(3.575,-1.625) L15(4.225,-1.625) L16(4.875,-1.625) M1(-4.875,-2.275) M2(-4.225,-2.275) M3(-3.575,-2.275) M4(-2.925,-2.275) M5(-2.275,-2.275) M6(-1.625,-2.275) M7(-0.975,-2.275) M8(-0.325,-2.275) M9(0.325,-2.275) M10(0.975,-2.275) M11(1.625,-2.275) M12(2.275,-2.275) M13(2.925,-2.275) M14(3.575,-2.275) M15(4.225,-2.275) M16(4.875,-2.275) N1(-4.875,-2.925) N2(-4.225,-2.925) N3(-3.575,-2.925) N4(-2.925,-2.925) N5(-2.275,-2.925) N6(-1.625,-2.925) N7(-0.975,-2.925) N8(-0.325,-2.925) N9(0.325,-2.925) N10(0.975,-2.925) N11(1.625,-2.925) N12(2.275,-2.925) N13(2.925,-2.925) N14(3.575,-2.925) N15(4.225,-2.925) N16(4.875,-2.925) P1(-4.875,-3.575) P2(-4.225,-3.575) P3(-3.575,-3.575) P4(-2.925,-3.575) P5(-2.275,-3.575) P6(-1.625,-3.575) P7(-0.975,-3.575) P8(-0.325,-3.575) P9(0.325,-3.575) P10(0.975,-3.575) P11(1.625,-3.575) P12(2.275,-3.575) P13(2.925,-3.575) P14(3.575,-3.575) P15(4.225,-3.575) P16(4.875,-3.575) R1(-4.875,-4.225) R2(-4.225,-4.225) R3(-3.575,-4.225) R4(-2.925,-4.225) R5(-2.275,-4.225) R6(-1.625,-4.225) R7(-0.975,-4.225) R8(-0.325,-4.225) R9(0.325,-4.225) R10(0.975,-4.225) R11(1.625,-4.225) R12(2.275,-4.225) R13(2.925,-4.225) R14(3.575,-4.225) R15(4.225,-4.225) R16(4.875,-4.225) T1(-4.875,-4.875) T2(-4.225,-4.875) T3(-3.575,-4.875) T4(-2.925,-4.875) T5(-2.275,-4.875) T6(-1.625,-4.875) T7(-0.975,-4.875) T8(-0.325,-4.875) T9(0.325,-4.875) T10(0.975,-4.875) T11(1.625,-4.875) T12(2.275,-4.875) T13(2.925,-4.875) T14(3.575,-4.875) T15(4.225,-4.875) T16(4.875,-4.875)
BTB2X30-050-F-SMD
  round 0.61 hole 0.61 unplated: (-8.3,1.5) (8.3,1.5)
  rect 0.305x1.651 smd: 1(-7.252,-1.825) 2(-7.252,1.825) 3(-6.752,-1.825) 4(-6.752,1.825) 5(-6.252,-1.825) 6(-6.252,1.825) 7(-5.752,-1.825) 8(-5.752,1.825) 9(-5.251,-1.825) 10(-5.251,1.825) 11(-4.751,-1.825) 12(-4.751,1.825) 13(-4.251,-1.825) 14(-4.251,1.825) 15(-3.751,-1.825) 16(-3.751,1.825) 17(-3.251,-1.825) 18(-3.251,1.825) 19(-2.751,-1.825) 20(-2.751,1.825) 21(-2.251,-1.825) 22(-2.251,1.825) 23(-1.751,-1.825) 24(-1.751,1.825) 25(-1.25,-1.825) 26(-1.25,1.825) 27(-0.75,-1.825) 28(-0.75,1.825) 29(-0.25,-1.825) 30(-0.25,1.825) 31(0.25,-1.825) 32(0.25,1.825) 33(0.75,-1.825) 34(0.75,1.825) 35(1.25,-1.825) 36(1.25,1.825) 37(1.75,-1.825) 38(1.75,1.825) 39(2.25,-1.825) 40(2.25,1.825) 41(2.751,-1.825) 42(2.751,1.825) 43(3.251,-1.825) 44(3.251,1.825) 45(3.751,-1.825) 46(3.751,1.825) 47(4.251,-1.825) 48(4.251,1.825) 49(4.751,-1.825) 50(4.751,1.825) 51(5.251,-1.825) 52(5.251,1.825) 53(5.751,-1.825) 54(5.751,1.825) 55(6.251,-1.825) 56(6.251,1.825) 57(6.752,-1.825) 58(6.752,1.825) 59(7.252,-1.825) 60(7.252,1.825)
C0402
  rect 0.635x0.508 smd: 1(-0.508,0) 2(0.508,0)
C0603
  rect 0.889x0.813 smd: 1(-0.762,0) 2(0.762,0)
C0805
  rect 1.016x1.397 smd: 1(-0.889,0) 2(0.889,0)
C1010_8383_6666
  rect 1.27x4.928 smd: 1(0,-3.352) 2(0,3.352)
C1206
  rect 1.397x1.651 smd: 1(-1.397,0) 2(1.397,0)
C1210
  rect 1.397x2.413 smd: 1(-1.397,0) 2(1.397,0)
CARD-MICRO-SD-9-80
  round 1.016 hole 1.016 unplated: (-4.928,-2.65) (3.072,-2.65)
  rect 0.711x1.6 smd: 1(2.221,7.926) 2(1.121,7.926) 3(0.022,7.926) 4(-1.078,7.926) 5(-2.179,7.926) 6(-3.278,7.926) 7(-4.378,7.926) 8(-5.479,7.926) 9(-6.579,7.926)
  rect 1.016x2.032 smd: 10(-7.931,7.35) 12(7.874,-2.25) 13(-7.931,-2.25)
  rect 1.397x1.6 smd: 11(6.821,7.35)
CON2-075053-036
  rect 1.778x2.54 smd: (-3.075,-0.167) (3.075,-0.167)
  rect 0.711x1.778 smd: 1(-0.625,-2.667) 2(0.625,-2.667)
D2215-95
  rect 2.159x2.743 smd: 1(-2.21,0) 2(2.21,0)
DFN6-065-0202-008-N
  rect 0.457x0.381 smd: 1(-0.975,0.65) 2(-0.975,0) 3(-0.975,-0.65) 4(0.975,-0.65) 5(0.975,0) 6(0.975,0.65)
  rect 0.991x1.6 smd: 7(0,0)
DFN10-050-0303-010-N
  rect 0.762x0.305 smd: 1(-1.4,1) 2(-1.4,0.5) 3(-1.4,0) 4(-1.4,-0.5) 5(-1.4,-1) 6(1.4,-1) 7(1.4,-0.5) 8(1.4,0) 9(1.4,0.5) 10(1.4,1)
  custom 0.412x0.412 smd: 11(0,0)
DSEN-PIR-D204B-3-193
  rect 1.143x1.143 hole 0.762: 1(1.796,1.796)
  round 1.143 hole 0.762: 2(-1.796,1.796) 3(-1.796,-1.796)
DSW3-087044-047-H
  oval 1.778x2.54 hole 1.016x1.778: (-4.15,0) (4.15,0)
  rect 1.524x1.524 hole 1.016: 1(-2,0)
  round 1.524 hole 1.016: 2(0,0) 3(2,0)
DSW4-KH-6X6X7H-ZJ
  round 1.778 hole 1.143: 1(-2.25,-1.25) 2(2.25,-1.25)
  round 1.905 hole 1.397: 3(-3.5,1.25) 4(3.5,1.25)
F1206
  rect 1.397x1.651 smd: 1(-1.397,0) 2(1.397,0)
FB0402
  rect 0.635x0.508 smd: 1(-0.508,0) 2(0.508,0)
FB0603
  rect 0.762x0.813 smd: 1(-0.762,0) 2(0.762,0)
FB1206
  rect 1.397x1.651 smd: 1(-1.397,0) 2(1.397,0)
FPC30-005-0520-75
  rect 0.305x1.016 smd: 1(7.248,0) 2(6.748,0) 3(6.248,0) 4(5.749,0) 5(5.249,0) 6(4.749,0) 7(4.249,0) 8(3.749,0) 9(3.249,0) 10(2.749,0) 11(2.249,0) 12(1.75,0) 13(1.25,0) 14(0.75,0) 15(0.25,0) 16(-0.25,0) 17(-0.75,0) 18(-1.25,0) 19(-1.75,0) 20(-2.249,0) 21(-2.749,0) 22(-3.249,0) 23(-3.749,0) 24(-4.249,0) 25(-4.749,0) 26(-5.249,0) 27(-5.749,0) 28(-6.248,0) 29(-6.748,0) 30(-7.248,0)
  rect 2.032x1.321 smd: 31(-9.548,-2.7) 32(9.548,-2.7)
HEAD2-100
  rect 1.524x1.524 hole 1.016: 1(0,0)
  round 1.524 hole 1.016: 2(2.54,0)
HEAD2X8-100
  rect 1.524x1.524 hole 1.016: 1(0,0)
  round 1.524 hole 1.016: 2(0,2.54) 3(2.54,0) 4(2.54,2.54) 5(5.08,0) 6(5.08,2.54) 7(7.62,0) 8(7.62,2.54) 9(10.16,0) 10(10.16,2.54) 11(12.7,0) 12(12.7,2.54) 13(15.24,0) 14(15.24,2.54) 15(17.78,0) 16(17.78,2.54)
HEAD2X15-100
  rect 1.524x1.524 hole 1.016: 1(0,0)
  round 1.524 hole 1.016: 2(0,2.54) 3(2.54,0) 4(2.54,2.54) 5(5.08,0) 6(5.08,2.54) 7(7.62,0) 8(7.62,2.54) 9(10.16,0) 10(10.16,2.54) 11(12.7,0) 12(12.7,2.54) 13(15.24,0) 14(15.24,2.54) 15(17.78,0) 16(17.78,2.54) 17(20.32,0) 18(20.32,2.54) 19(22.86,0) 20(22.86,2.54) 21(25.4,0) 22(25.4,2.54) 23(27.94,0) 24(27.94,2.54) 25(30.48,0) 26(30.48,2.54) 27(33.02,0) 28(33.02,2.54) 29(35.56,0) 30(35.56,2.54)
HEAD3-100
  rect 1.524x1.524 hole 1.016: 1(0,0)
  round 1.524 hole 1.016: 2(2.54,0) 3(5.08,0)
HEAD4-100
  rect 1.524x1.524 hole 1.016: 1(0,0)
  round 1.524 hole 1.016: 2(2.54,0) 3(5.08,0) 4(7.62,0)
HEAD6-100
  rect 1.524x1.524 hole 1.016: 1(0,0)
  round 1.524 hole 1.016: 2(2.54,0) 3(5.08,0) 4(7.62,0) 5(10.16,0) 6(12.7,0)
HEAD10-100
  rect 1.524x1.524 hole 1.016: 1(-7.62,0)
  round 1.524 hole 1.016: 2(-5.08,0) 3(-2.54,0) 4(0,0) 5(2.54,0) 6(5.08,0) 7(7.62,0) 8(10.16,0) 9(12.7,0) 10(15.24,0)
HOLE-M3
  round 5.969 hole 3.175: 1(0,0)
ID
  round 1.016 smd: 1(0,0)
LED0603
  rect 0.762x0.813 smd: 1(-0.762,0) 2(0.762,0)
MIC4-030040-012
  round 0.762 hole 0.762 unplated: (0.653,0)
  rect 0.762x0.508 smd: 1(-1.437,0.88) 2(-1.437,0) 3(-1.437,-0.88)
  custom 0.533x0.533 smd: 4(-0.262,0)
PL02_502-01
  rect 0.762x2.413 smd: 1(-1.016,0) 2(1.016,0)
PL0404-020
  rect 3.048x1.524 smd: 1(0,1.549) 2(0,-1.549)
PL0505-030
  rect 1.524x2.032 smd: 1(-2.112,0) 2(2.112,0)
QFN8-050-0202-008-N
  rect 0.305x0.457 smd: 1(-0.75,-0.979) 2(-0.25,-0.979) 3(0.25,-0.979) 4(0.75,-0.979) 5(0.75,0.979) 6(0.25,0.979) 7(-0.25,0.979) 8(-0.75,0.979)
  rect 1.524x0.889 smd: 9(0,0)
QFN9-050-025015-010
  rect 0.254x0.559 smd: 1(-0.5,1.175) 4(-0.5,-1.175) 5(0,-1.175) 6(0.5,-1.175) 8(0.5,1.175) 9(0,1.175)
  rect 1.016x0.203 smd: 2(-0.475,0.4) 3(-0.475,-0.4) 7(0.475,0)
QFN12-040-018018-006
  rect 0.762x0.203 smd: 1(-0.9,0.2) 2(-0.9,-0.2) 7(0.9,-0.2) 8(0.9,0.2)
  rect 0.203x0.762 smd: 3(-0.6,-0.9) 4(-0.2,-0.9) 5(0.2,-0.9) 6(0.6,-0.9) 9(0.6,0.9) 10(0.2,0.9) 11(-0.2,0.9) 12(-0.6,0.9)
QFN16-050-0303-008-N
  oval 0.838x0.254 smd: 1(-1.475,0.75) 2(-1.475,0.25) 3(-1.475,-0.25) 4(-1.475,-0.75) 9(1.475,-0.75) 10(1.475,-0.25) 11(1.475,0.25) 12(1.475,0.75)
  oval 0.254x0.838 smd: 5(-0.75,-1.475) 6(-0.25,-1.475) 7(0.25,-1.475) 8(0.75,-1.475) 13(0.75,1.475) 14(0.25,1.475) 15(-0.25,1.475) 16(-0.75,1.475)
  rect 1.6x1.6 smd: 17(0,0)
R0402
  rect 0.635x0.508 smd: 1(-0.508,0) 2(0.508,0)
R0603
  rect 0.762x0.813 smd: 1(-0.762,0) 2(0.762,0)
R1206
  rect 1.397x1.651 smd: 1(-1.397,0) 2(1.397,0)
SOD123FL-2-40
  rect 0.914x1.219 smd: 1(-1.651,0) 2(1.651,0)
SOD523-2-28
  rect 0.508x0.406 smd: 1(-0.889,0) 2(0.889,0)
SOD523-2-28-H
  rect 0.508x0.406 smd: 1(-0.66,0) 2(0.66,0)
SOP8-26-120-43-N
  rect 1.524x0.381 smd: 1(-2.2,0.975) 2(-2.2,0.325) 3(-2.2,-0.325) 4(-2.2,-0.975) 5(2.2,-0.975) 6(2.2,-0.325) 7(2.2,0.325) 8(2.2,0.975)
  rect 1.524x1.778 smd: 9(0,0)
SOP8-50-210-85
  rect 0.508x1.778 smd: 1(-1.905,-3.35) 2(-0.635,-3.35) 3(0.635,-3.35) 4(1.905,-3.35) 5(1.905,3.35) 6(0.635,3.35) 7(-0.635,3.35) 8(-1.905,3.35)
SOP10-40-153
  rect 0.635x1.524 smd: 1(-2,-2.667) 2(-1,-2.667) 3(0,-2.667) 4(1,-2.667) 5(2,-2.667) 6(2,2.667) 7(1,2.667) 8(0,2.667) 9(-1,2.667) 10(-2,2.667)
  rect 3.302x2.286 smd: 11(0,0)
SOT23-3-43
  rect 0.762x0.889 smd: 1(-0.95,-1.143) 2(0.95,-1.143) 3(0,1.143)
SOT23-5-36
  rect 0.635x1.016 smd: 1(-0.953,-1.295) 2(0,-1.295) 3(0.953,-1.295) 4(0.953,1.295) 5(-0.953,1.295)
SOT23-5-57
  rect 0.635x1.016 smd: 1(-0.953,-1.245) 2(0,-1.245) 3(0.953,-1.245) 4(0.953,1.245) 5(-0.953,1.245)
SOT143-4-48
  rect 1.016x1.143 smd: 1(-0.747,-1.143)
  rect 0.635x1.143 smd: 2(0.953,-1.143) 3(0.953,1.143) 4(-0.953,1.143)
SW2-061036-025
  rect 2.032x1.016 smd: 1(3.016,0) 2(-3.016,0)
SW4-100-060050-035
  rect 1.016x2.159 smd: 1(-1.27,-4.386) 2(1.27,-4.386) 3(-1.27,4.386) 4(1.27,4.386)
